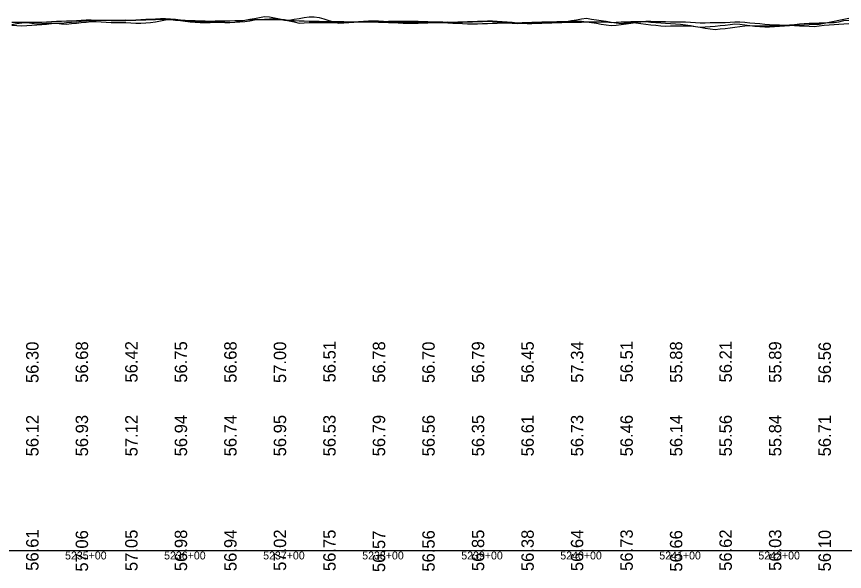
# Model space of a CAD drawing. Extents: x 2147288 to 2220488, y 740833 to 759333.
# Drawn here: x 2205808 to 2206644, y 750062 to 750622 of the extents above; entities that cross this region are included whole.
import ezdxf

# ---------------------------------------------------------------- set-up
doc = ezdxf.new("R2010")
doc.units = 0
for name, color, linetype in [('RD_DDB_Profile_EX', 7, 'Continuous'), ('RD_DDB_StaTX', 7, 'Continuous'), ('RD_DDB_StripGrade', 7, 'Continuous'), ('RD_GPK_Profile_Cell', 7, 'Continuous')]:
    doc.layers.add(name, color=color, linetype=linetype)

msp = doc.modelspace()

# ---------------------------------------------------------------- linework, layer by layer
at = {"layer": 'RD_DDB_Profile_EX'}
for points in [[(2205803.28, 750613.37), (2205808.28, 750613.15), (2205813.28, 750612.92), (2205818.28, 750613.08), (2205823.28, 750613.41), (2205828.28, 750613.82), (2205833.28, 750614.22), (2205838.28, 750614.63), (2205843.28, 750615.03), (2205848.28, 750615.44), (2205853.28, 750615.56), (2205858.28, 750616.02), (2205863.28, 750616.47), (2205868.28, 750616.92), (2205873.28, 750617.38), (2205878.28, 750617.83), (2205883.28, 750618.28), (2205888.28, 750618.43), (2205893.28, 750618.47), (2205898.28, 750618.52), (2205903.28, 750618.56), (2205908.28, 750618.6), (2205913.28, 750618.65), (2205918.28, 750618.69), (2205923.28, 750618.65), (2205928.28, 750618.89), (2205933.28, 750619.12), (2205938.28, 750619.36), (2205943.28, 750619.6), (2205948.28, 750619.84), (2205953.28, 750620.08), (2205958.28, 750620.33), (2205963.28, 750619.85), (2205968.28, 750619.37), (2205973.28, 750618.89), (2205978.28, 750618.4), (2205983.28, 750617.92), (2205988.28, 750617.44), (2205993.28, 750617.18), (2205998.28, 750617.03), (2206003.28, 750616.89), (2206008.28, 750616.74), (2206013.28, 750616.59), (2206018.28, 750616.44), (2206023.28, 750616.29), (2206028.28, 750616.64), (2206033.28, 750617.55), (2206038.28, 750618.47)], [(2205803.28, 750616.41), (2205808.28, 750616.41), (2205813.28, 750616.42), (2205818.28, 750616.42), (2205823.28, 750616.43), (2205828.28, 750616.43), (2205833.28, 750616.55), (2205838.28, 750616.9), (2205843.28, 750617.12), (2205848.28, 750617.33), (2205853.28, 750617.55), (2205858.28, 750617.76), (2205863.28, 750617.98), (2205868.28, 750618.2), (2205873.28, 750618.46), (2205878.28, 750618.8), (2205883.28, 750618.69), (2205888.28, 750618.58), (2205893.28, 750618.48), (2205898.28, 750618.37), (2205903.28, 750618.26), (2205908.28, 750618.16), (2205913.28, 750618.08), (2205918.28, 750618.17), (2205923.28, 750618.38), (2205928.28, 750618.57), (2205933.28, 750618.76), (2205938.28, 750618.95), (2205943.28, 750619.14), (2205948.28, 750619.33), (2205953.28, 750619.52), (2205958.28, 750619.48), (2205963.28, 750619.02), (2205968.28, 750618.82), (2205973.28, 750618.63), (2205978.28, 750618.44), (2205983.28, 750618.25), (2205988.28, 750618.05), (2205993.28, 750617.86), (2205998.28, 750617.68), (2206003.28, 750617.57), (2206008.28, 750617.67), (2206013.28, 750617.78), (2206018.28, 750617.88), (2206023.28, 750617.99), (2206028.28, 750618.09), (2206033.28, 750618.2), (2206038.28, 750618.43)], [(2205803.28, 750614.2), (2205808.28, 750614.97), (2205813.28, 750615.85), (2205818.28, 750616.11), (2205823.28, 750615.39), (2205828.28, 750614.72), (2205833.28, 750615.13), (2205838.28, 750615.54), (2205843.28, 750615.94), (2205848.28, 750615.31), (2205853.28, 750614.66), (2205858.28, 750614.55), (2205863.28, 750615.09), (2205868.28, 750615.64), (2205873.28, 750616.13), (2205878.28, 750616.58), (2205883.28, 750617.03), (2205888.28, 750617.02), (2205893.28, 750616.68), (2205898.28, 750616.34), (2205903.28, 750616.15), (2205908.28, 750616.2), (2205913.28, 750616.24), (2205918.28, 750616.07), (2205923.28, 750615.83), (2205928.28, 750615.59), (2205933.28, 750615.51), (2205938.28, 750615.75), (2205943.28, 750616.03), (2205948.28, 750616.92), (2205953.28, 750617.82), (2205958.28, 750618.72), (2205963.28, 750619.06), (2205968.28, 750618.57), (2205973.28, 750618.06), (2205978.28, 750617.49), (2205983.28, 750616.92), (2205988.28, 750616.36), (2205993.28, 750616.11), (2205998.28, 750616.2), (2206003.28, 750616.29), (2206008.28, 750616.39), (2206013.28, 750616.36), (2206018.28, 750616.21), (2206023.28, 750616.31), (2206028.28, 750616.64), (2206033.28, 750616.96), (2206038.28, 750617.28)], [(2206038.28, 750618.47), (2206043.28, 750619.38), (2206048.28, 750620.3), (2206053.28, 750621.21), (2206058.28, 750622.13), (2206063.28, 750621.91), (2206068.28, 750620.86), (2206073.28, 750619.81), (2206078.28, 750618.76), (2206083.28, 750617.71), (2206088.28, 750616.66), (2206093.28, 750615.61), (2206098.28, 750615.92), (2206103.28, 750616), (2206108.28, 750616.07), (2206113.28, 750616.14), (2206118.28, 750616.22), (2206123.28, 750616.29), (2206128.28, 750616.26), (2206133.28, 750615.91), (2206138.28, 750616.24), (2206143.28, 750616.57), (2206148.28, 750616.9), (2206153.28, 750617.23), (2206158.28, 750617.56), (2206163.28, 750617.88), (2206168.28, 750617.89), (2206173.28, 750617.69), (2206178.28, 750617.5), (2206183.28, 750617.31), (2206188.28, 750617.12), (2206193.28, 750616.92), (2206198.28, 750616.77), (2206203.28, 750616.73), (2206208.28, 750616.64), (2206213.28, 750616.55), (2206218.28, 750616.46), (2206223.28, 750616.37), (2206228.28, 750616.28), (2206233.28, 750616.18), (2206238.28, 750616), (2206243.28, 750615.79), (2206248.28, 750615.57), (2206253.28, 750615.36), (2206258.28, 750615.15), (2206263.28, 750614.94), (2206268.28, 750614.8), (2206273.28, 750614.96), (2206278.28, 750615.11), (2206283.28, 750615.26), (2206288.28, 750615.41), (2206293.28, 750615.56), (2206298.28, 750615.71), (2206303.28, 750615.73), (2206308.28, 750615.67), (2206313.28, 750615.84), (2206318.28, 750616.02), (2206323.28, 750616.19), (2206328.28, 750616.37), (2206333.28, 750616.54), (2206338.28, 750616.7), (2206343.28, 750616.8), (2206348.28, 750616.91), (2206353.28, 750617.02), (2206358.28, 750617.13), (2206363.28, 750617.24), (2206368.28, 750617.34), (2206373.28, 750617.64), (2206378.28, 750617.51), (2206383.28, 750616.78), (2206388.28, 750616.06), (2206393.28, 750615.34), (2206398.28, 750614.62), (2206403.28, 750613.89), (2206408.28, 750613.16), (2206413.28, 750613.31), (2206418.28, 750613.99), (2206423.28, 750614.68), (2206428.28, 750615.37), (2206433.28, 750616.05), (2206438.28, 750616.74), (2206443.28, 750617.04), (2206448.28, 750616.58), (2206453.28, 750616.2), (2206458.28, 750615.83), (2206463.28, 750615.45), (2206468.28, 750615.07), (2206473.28, 750614.69), (2206478.28, 750614.43), (2206483.28, 750613.87), (2206488.28, 750613.02), (2206493.28, 750612.16), (2206498.28, 750611.31), (2206503.28, 750610.45), (2206508.28, 750609.6), (2206513.28, 750609.07), (2206518.28, 750609.64), (2206523.28, 750610.25), (2206528.28, 750610.87), (2206533.28, 750611.48), (2206538.28, 750612.09)], [(2206038.28, 750617.28), (2206043.28, 750617.94), (2206048.28, 750618.86), (2206053.28, 750619.34), (2206058.28, 750619.54), (2206063.28, 750619.74), (2206068.28, 750619.94), (2206073.28, 750619.4), (2206078.28, 750618.35), (2206083.28, 750618.47), (2206088.28, 750619.38), (2206093.28, 750620.29), (2206098.28, 750621.21), (2206103.28, 750621.72), (2206108.28, 750621.79), (2206113.28, 750621.17), (2206118.28, 750619.68), (2206123.28, 750618.19), (2206128.28, 750616.69), (2206133.28, 750615.41), (2206138.28, 750615.74), (2206143.28, 750616.07), (2206148.28, 750616.39), (2206153.28, 750616.7), (2206158.28, 750617.02), (2206163.28, 750617.34), (2206168.28, 750617.66), (2206173.28, 750617.47), (2206178.28, 750617.28), (2206183.28, 750617.34), (2206188.28, 750617.4), (2206193.28, 750617.46), (2206198.28, 750617.52), (2206203.28, 750617.58), (2206208.28, 750617.51), (2206213.28, 750617.42), (2206218.28, 750617.28), (2206223.28, 750617.13), (2206228.28, 750616.98), (2206233.28, 750616.84), (2206238.28, 750616.69), (2206243.28, 750616.5), (2206248.28, 750616.29), (2206253.28, 750616.38), (2206258.28, 750616.57), (2206263.28, 750616.75), (2206268.28, 750616.94), (2206273.28, 750617.12), (2206278.28, 750617.29), (2206283.28, 750617.44), (2206288.28, 750617.21), (2206293.28, 750616.76), (2206298.28, 750616.31), (2206303.28, 750615.86), (2206308.28, 750615.42), (2206313.28, 750615.24), (2206318.28, 750615.41), (2206323.28, 750615.54), (2206328.28, 750615.63), (2206333.28, 750615.71), (2206338.28, 750615.8), (2206343.28, 750615.88), (2206348.28, 750615.97), (2206353.28, 750616.08), (2206358.28, 750616.48), (2206363.28, 750617.31), (2206368.28, 750618.14), (2206373.28, 750618.97), (2206378.28, 750619.79), (2206383.28, 750620.35), (2206388.28, 750619.62), (2206393.28, 750618.89), (2206398.28, 750618.11), (2206403.28, 750617.34), (2206408.28, 750616.56), (2206413.28, 750615.79), (2206418.28, 750615.11), (2206423.28, 750615.79), (2206428.28, 750616.29), (2206433.28, 750615.69), (2206438.28, 750615.1), (2206443.28, 750614.5), (2206448.28, 750613.9), (2206453.28, 750613.31), (2206458.28, 750612.92), (2206463.28, 750612.55), (2206468.28, 750612.62), (2206473.28, 750612.7), (2206478.28, 750612.77), (2206483.28, 750612.85), (2206488.28, 750612.93), (2206493.28, 750612.18), (2206498.28, 750611.33), (2206503.28, 750611.62), (2206508.28, 750612.1), (2206513.28, 750612.59), (2206518.28, 750613.07), (2206523.28, 750613.55), (2206528.28, 750614.14), (2206533.28, 750614.76), (2206538.28, 750614.48)], [(2206038.28, 750618.43), (2206043.28, 750619.24), (2206048.28, 750619.23), (2206053.28, 750619.22), (2206058.28, 750619.22), (2206063.28, 750619.21), (2206068.28, 750619.2), (2206073.28, 750619.19), (2206078.28, 750619.1), (2206083.28, 750618.12), (2206088.28, 750618), (2206093.28, 750617.88), (2206098.28, 750617.75), (2206103.28, 750617.63), (2206108.28, 750617.51), (2206113.28, 750617.39), (2206118.28, 750617.29), (2206123.28, 750617.35), (2206128.28, 750617.24), (2206133.28, 750617.14), (2206138.28, 750617.04), (2206143.28, 750616.93), (2206148.28, 750616.83), (2206153.28, 750616.73), (2206158.28, 750616.67), (2206163.28, 750616.98), (2206168.28, 750616.79), (2206173.28, 750616.59), (2206178.28, 750616.4), (2206183.28, 750616.21), (2206188.28, 750616.01), (2206193.28, 750615.82), (2206198.28, 750615.62), (2206203.28, 750615.43), (2206208.28, 750615.35), (2206213.28, 750615.54), (2206218.28, 750615.74), (2206223.28, 750615.93), (2206228.28, 750616.12), (2206233.28, 750616.32), (2206238.28, 750616.51), (2206243.28, 750616.7), (2206248.28, 750616.5), (2206253.28, 750616.67), (2206258.28, 750616.85), (2206263.28, 750617.03), (2206268.28, 750617.21), (2206273.28, 750617.39), (2206278.28, 750617.58), (2206283.28, 750617.76), (2206288.28, 750617.9), (2206293.28, 750617.51), (2206298.28, 750617.12), (2206303.28, 750616.73), (2206308.28, 750616.34), (2206313.28, 750615.95), (2206318.28, 750615.56), (2206323.28, 750615.16), (2206328.28, 750615.25), (2206333.28, 750615.42), (2206338.28, 750615.6), (2206343.28, 750615.78), (2206348.28, 750615.96), (2206353.28, 750616.13), (2206358.28, 750616.31), (2206363.28, 750616.49), (2206368.28, 750616.61), (2206373.28, 750616.64), (2206378.28, 750616.64), (2206383.28, 750616.65), (2206388.28, 750616.65), (2206393.28, 750616.66), (2206398.28, 750616.66), (2206403.28, 750616.67), (2206408.28, 750616.15), (2206413.28, 750616.44), (2206418.28, 750616.73), (2206423.28, 750616.86), (2206428.28, 750616.99), (2206433.28, 750617.13), (2206438.28, 750617.26), (2206443.28, 750617.39), (2206448.28, 750617.53), (2206453.28, 750617.29), (2206458.28, 750617.12), (2206463.28, 750617.04), (2206468.28, 750616.95), (2206473.28, 750616.87), (2206478.28, 750616.78), (2206483.28, 750616.7), (2206488.28, 750616.62), (2206493.28, 750616.15), (2206498.28, 750615.79), (2206503.28, 750615.89), (2206508.28, 750616), (2206513.28, 750616.1), (2206518.28, 750616.2), (2206523.28, 750616.31), (2206528.28, 750616.41), (2206533.28, 750616.66), (2206538.28, 750616.75)], [(2206538.28, 750612.09), (2206543.28, 750612.71), (2206548.28, 750613.03), (2206553.28, 750612.82), (2206558.28, 750612.77), (2206563.28, 750612.72), (2206568.28, 750612.67), (2206573.28, 750612.63), (2206578.28, 750612.58), (2206583.28, 750612.67), (2206588.28, 750613.02), (2206593.28, 750613.29), (2206598.28, 750613.55), (2206603.28, 750613.82), (2206608.28, 750614.09), (2206613.28, 750614.35), (2206618.28, 750614.6), (2206623.28, 750615.38), (2206628.28, 750616.41), (2206633.28, 750617.44), (2206638.28, 750618.47), (2206643.28, 750619.5), (2206648.28, 750620.54)], [(2206538.28, 750614.48), (2206543.28, 750613.85), (2206548.28, 750613.23), (2206553.28, 750612.6), (2206558.28, 750611.98), (2206563.28, 750611.82), (2206568.28, 750611.77), (2206573.28, 750612.05), (2206578.28, 750612.58), (2206583.28, 750613.11), (2206588.28, 750613.64), (2206593.28, 750614.18), (2206598.28, 750614.71), (2206603.28, 750615.05), (2206608.28, 750615.31), (2206613.28, 750615.54), (2206618.28, 750615.73), (2206623.28, 750615.92), (2206628.28, 750616.11), (2206633.28, 750616.3), (2206638.28, 750616.97), (2206643.28, 750618), (2206648.28, 750618.6)], [(2206538.28, 750616.75), (2206543.28, 750616.32), (2206548.28, 750615.89), (2206553.28, 750615.45), (2206558.28, 750615.02), (2206563.28, 750614.59), (2206568.28, 750614.15), (2206573.28, 750613.83), (2206578.28, 750613.7), (2206583.28, 750613.49), (2206588.28, 750613.29), (2206593.28, 750613.08), (2206598.28, 750612.87), (2206603.28, 750612.66), (2206608.28, 750612.46), (2206613.28, 750612.25), (2206618.28, 750612.78), (2206623.28, 750613.34), (2206628.28, 750613.71), (2206633.28, 750614.08), (2206638.28, 750614.45), (2206643.28, 750614.82), (2206648.28, 750615.19)]]:
    msp.add_lwpolyline(points, dxfattribs=at)
at = {"layer": 'RD_GPK_Profile_Cell'}
msp.add_line((2198888.28, 750083.43), (2220488.28, 750083.43), dxfattribs=at)

# ---------------------------------------------------------------- texts
at = {"layer": 'RD_DDB_Profile_EX'}
for s, p in [('56.30', (2205830.08, 750252.38)), ('56.68', (2205880.08, 750252.64)), ('56.42', (2205930.08, 750252.89)), ('56.75', (2205980.08, 750252.69)), ('56.68', (2206030.08, 750252.64)), ('57.00', (2206080.08, 750252.38)), ('56.51', (2206130.08, 750253)), ('56.78', (2206180.08, 750252.64)), ('56.70', (2206230.08, 750252.38)), ('56.79', (2206280.08, 750252.64)), ('56.45', (2206330.08, 750252.69)), ('57.34', (2206380.08, 750252.66)), ('56.51', (2206430.08, 750253)), ('55.88', (2206480.08, 750252.64)), ('56.21', (2206530.08, 750253)), ('55.89', (2206580.08, 750252.64)), ('56.56', (2206630.08, 750252.13)), ('56.61', (2205830.08, 750063)), ('57.06', (2205880.08, 750062.13)), ('57.05', (2205930.08, 750062.69)), ('56.98', (2205980.08, 750062.64)), ('56.94', (2206030.08, 750062.66)), ('57.02', (2206080.08, 750062.89)), ('56.75', (2206130.08, 750062.69)), ('56.57', (2206180.08, 750061.67)), ('56.56', (2206230.08, 750062.13)), ('56.85', (2206280.08, 750062.69)), ('56.38', (2206330.08, 750062.64)), ('56.64', (2206380.08, 750062.66)), ('56.73', (2206430.08, 750062.89)), ('56.66', (2206480.08, 750062.13)), ('56.62', (2206530.08, 750062.89)), ('56.03', (2206580.08, 750062.89)), ('56.10', (2206630.08, 750062.38))]:
    msp.add_text(s, height=12.5, rotation=90, dxfattribs=at).set_placement(p)
at = {"layer": 'RD_DDB_StaTX'}
for s, p in [('5235+00', (2205856.88, 750074.43)), ('5235+00', (2205856.88, 750074.43)), ('5235+00', (2205856.88, 750074.43)), ('5236+00', (2205956.88, 750074.43)), ('5236+00', (2205956.88, 750074.43)), ('5236+00', (2205956.88, 750074.43)), ('5237+00', (2206056.88, 750074.43)), ('5237+00', (2206056.88, 750074.43)), ('5237+00', (2206056.88, 750074.43)), ('5238+00', (2206156.88, 750074.43)), ('5238+00', (2206156.88, 750074.43)), ('5238+00', (2206156.88, 750074.43)), ('5239+00', (2206256.88, 750074.43)), ('5239+00', (2206256.88, 750074.43)), ('5239+00', (2206256.88, 750074.43)), ('5240+00', (2206356.88, 750074.43)), ('5240+00', (2206356.88, 750074.43)), ('5240+00', (2206356.88, 750074.43)), ('5241+00', (2206456.88, 750074.43)), ('5241+00', (2206456.88, 750074.43)), ('5241+00', (2206456.88, 750074.43)), ('5242+00', (2206556.88, 750074.43)), ('5242+00', (2206556.88, 750074.43)), ('5242+00', (2206556.88, 750074.43))]:
    msp.add_text(s, height=8, dxfattribs=at).set_placement(p)
at = {"layer": 'RD_DDB_StripGrade'}
for s, p in [('56.12', (2205830.08, 750178.43)), ('56.93', (2205880.08, 750178.43)), ('57.12', (2205930.08, 750178.43)), ('56.94', (2205980.08, 750178.43)), ('56.74', (2206030.08, 750178.43)), ('56.95', (2206080.08, 750178.43)), ('56.53', (2206130.08, 750178.43)), ('56.79', (2206180.08, 750178.43)), ('56.56', (2206230.08, 750178.43)), ('56.35', (2206280.08, 750178.43)), ('56.61', (2206330.08, 750178.43)), ('56.73', (2206380.08, 750178.43)), ('56.46', (2206430.08, 750178.43)), ('56.14', (2206480.08, 750178.43)), ('55.56', (2206530.08, 750178.43)), ('55.84', (2206580.08, 750178.43)), ('56.71', (2206630.08, 750178.43))]:
    msp.add_text(s, height=12.5, rotation=90, dxfattribs=at).set_placement(p)

doc.saveas('drawing.dxf')
